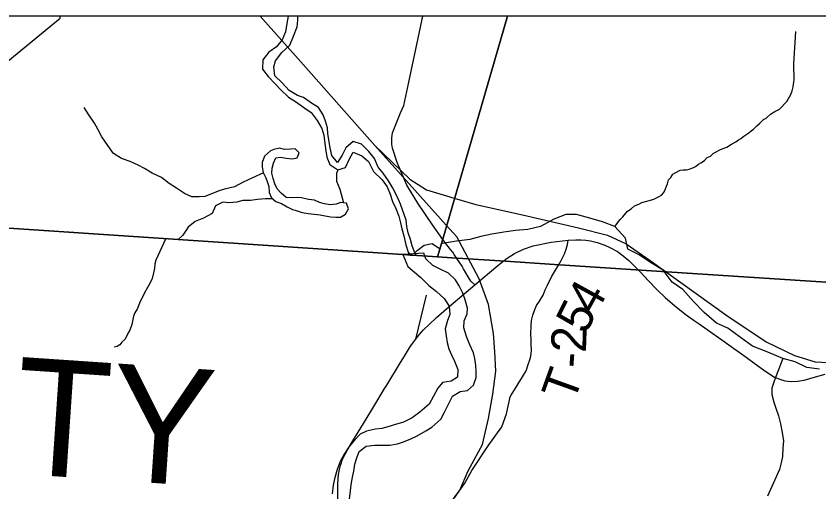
# Model space of a CAD drawing. Extents: x 0 to 44, y -23.8 to 22.
# Drawn here: x 6.018 to 7.321, y 20.128 to 20.9 of the extents above; entities that cross this region are included whole.
import ezdxf

# ---------------------------------------------------------------- set-up
doc = ezdxf.new("R2010")
doc.units = 0
for name, color, linetype in [('Default', 7, 'Continuous'), ('GM_X_County_Road', 7, 'Continuous'), ('GM_X_County_Text', 7, 'Continuous'), ('GM_X_Minor_Lake', 7, 'Continuous'), ('GM_X_Minor_River', 7, 'Continuous'), ('GM_X_Rail_Line', 7, 'Continuous'), ('GM_X_State_Route', 7, 'Continuous'), ('GM_X_Township_Road', 7, 'Continuous'), ('GM_X_Township_Road_Text', 7, 'Continuous'), ('SH_Cut_Line', 7, 'Continuous')]:
    doc.layers.add(name, color=color, linetype=linetype)

msp = doc.modelspace()

# ---------------------------------------------------------------- linework, layer by layer
at = {"layer": 'Default'}
for points in [[(6.8158, 20.9), (2.3497, 20.9), (2.472, 20.6113), (2.8013, 19.8369), (3.0092, 19.3427), (3.0496, 19.2474), (3.1321, 19.0527), (3.1789, 18.9421), (3.455, 18.29), (3.5135, 19.1552), (3.5139, 19.1608), (3.5639, 19.9016), (3.5995, 20.4294), (3.5996, 20.4304), (3.6002, 20.4391), (3.6191, 20.7184), (3.9141, 20.6975), (4.3639, 20.6657), (6.7023, 20.5094), (6.7107, 20.5383)], [(6.0898, 20.9), (5.0097, 20.9), (4.9745, 20.6293), (5.6255, 20.5903), (5.7098, 20.5851), (6.0899, 20.8964)], [(8.9, 20.3521), (8.9, 20.9), (6.8158, 20.9), (6.7107, 20.5383), (6.7023, 20.5094), (6.7257, 20.5079), (6.8124, 20.5023), (6.892, 20.4972), (7.016, 20.4891), (7.4495, 20.4611), (7.6577, 20.4476), (8.6785, 20.3684)]]:
    msp.add_lwpolyline(points, close=True, dxfattribs=at)
msp.add_lwpolyline([(7.4495, 20.4611), (7.016, 20.4891), (6.892, 20.4972), (6.8124, 20.5023), (6.7257, 20.5079), (6.7023, 20.5094), (4.3639, 20.6657), (3.9141, 20.6975), (3.6191, 20.7184), (3.6002, 20.4391), (3.5996, 20.4304), (3.5995, 20.4294), (3.5639, 19.9016), (3.5139, 19.1608), (3.5135, 19.1552), (3.455, 18.29), (3.763, 17.5087), (3.7907, 17.4383), (4.026, 16.9163), (4.1422, 16.6361), (4.3476, 16.1408)], dxfattribs=at)
at = {"layer": 'GM_X_County_Road'}
msp.add_line((6.667, 20.376), (6.6844, 20.4475), dxfattribs=at)
for points in [[(6.7109, 20.5378), (6.694, 20.5615), (6.6703, 20.5965), (6.6525, 20.6256), (6.6474, 20.6369), (6.6366, 20.6627), (6.6294, 20.6856), (6.628, 20.6924), (6.6283, 20.7026), (6.6294, 20.7104), (6.642, 20.7432), (6.6477, 20.7548), (6.6555, 20.7928), (6.6708, 20.8641), (6.6787, 20.9)], [(6.5403, 20.116), (6.5403, 20.1283), (6.5405, 20.141), (6.5411, 20.1499), (6.5417, 20.1559), (6.543, 20.1643), (6.5449, 20.1717), (6.5462, 20.1756), (6.5478, 20.1799), (6.5496, 20.1843), (6.5522, 20.1893), (6.5555, 20.1952), (6.5649, 20.2113), (6.5824, 20.2394), (6.5975, 20.2643), (6.5989, 20.2666), (6.6159, 20.2946), (6.6199, 20.3013), (6.6406, 20.3356), (6.6502, 20.3512), (6.6586, 20.3644), (6.667, 20.376)]]:
    msp.add_lwpolyline(points, dxfattribs=at)
at = {"layer": 'GM_X_Minor_Lake'}
for points in [[(6.4813, 20.605), (6.4756, 20.6056), (6.4665, 20.6052), (6.4566, 20.606), (6.4483, 20.6129), (6.4419, 20.6197), (6.4381, 20.6281), (6.4355, 20.6364), (6.4333, 20.6452), (6.4337, 20.6531), (6.436, 20.6615), (6.4398, 20.6698), (6.4481, 20.6709), (6.4568, 20.6697), (6.4663, 20.6682), (6.4743, 20.6701), (6.4777, 20.6784), (6.4713, 20.6845), (6.4637, 20.6841), (6.4539, 20.6834), (6.4459, 20.6857), (6.4368, 20.6838), (6.4311, 20.6812), (6.4216, 20.6729), (6.4178, 20.6623), (6.4178, 20.6547), (6.4193, 20.6464), (6.4234, 20.6376), (6.4256, 20.6315), (6.4283, 20.6236), (6.429, 20.6141), (6.4331, 20.6053), (6.4399, 20.5993), (6.449, 20.5958), (6.4585, 20.5905), (6.4668, 20.5863), (6.4711, 20.585)], [(6.4711, 20.585), (6.4743, 20.584), (6.4827, 20.5813), (6.4925, 20.5797), (6.502, 20.5785), (6.5118, 20.5774), (6.5198, 20.5758), (6.5289, 20.5743), (6.5372, 20.5739), (6.5451, 20.5738), (6.5531, 20.5787), (6.5577, 20.5874), (6.5547, 20.5965), (6.5456, 20.5977), (6.538, 20.5947), (6.5282, 20.5936), (6.5191, 20.5952), (6.5108, 20.5978), (6.5024, 20.6013), (6.493, 20.6025), (6.4813, 20.605)]]:
    msp.add_lwpolyline(points, dxfattribs=at)
at = {"layer": 'GM_X_Minor_River'}
for p, q in [((6.6799, 20.5152), (6.646, 20.5131)), ((6.6578, 20.512), (6.6677, 20.5114))]:
    msp.add_line(p, q, dxfattribs=at)
for points in [[(6.4601, 20.9), (6.458, 20.8878), (6.4556, 20.8742), (6.4499, 20.8613), (6.4412, 20.85), (6.4283, 20.8413), (6.4187, 20.8288), (6.4183, 20.814), (6.4274, 20.8022)], [(6.4601, 20.9), (6.458, 20.8878), (6.4556, 20.8742), (6.4499, 20.8613), (6.4412, 20.85), (6.4283, 20.8413), (6.4187, 20.8288), (6.4183, 20.814), (6.4274, 20.8022)], [(6.4848, 20.7679), (6.475, 20.7713), (6.4614, 20.7793), (6.4504, 20.7915), (6.438, 20.8033), (6.4365, 20.8174), (6.4396, 20.8276), (6.4498, 20.8408), (6.4624, 20.8529), (6.4685, 20.8673), (6.4746, 20.8828), (6.4758, 20.8935), (6.4758, 20.9)], [(6.9902, 20.5586), (6.9986, 20.57), (7.0032, 20.5745), (7.0109, 20.5835), (7.0167, 20.5876), (7.022, 20.5921), (7.0293, 20.595), (7.0339, 20.5976), (7.0399, 20.5995), (7.0479, 20.6016), (7.0536, 20.6031), (7.062, 20.6072), (7.0659, 20.6094), (7.0697, 20.6139), (7.0721, 20.6196), (7.074, 20.6241), (7.0756, 20.6279), (7.0772, 20.6343), (7.081, 20.6381), (7.0841, 20.6438), (7.0891, 20.6464), (7.0959, 20.6501), (7.1009, 20.6504), (7.1062, 20.6507), (7.1107, 20.6518), (7.1165, 20.654), (7.121, 20.6558), (7.126, 20.6596), (7.1298, 20.6618), (7.1356, 20.6655), (7.1398, 20.6704), (7.1451, 20.673), (7.1497, 20.6771), (7.1535, 20.6794), (7.1616, 20.6838), (7.1658, 20.6853), (7.1719, 20.6875), (7.1795, 20.692), (7.1864, 20.696), (7.1906, 20.699), (7.1944, 20.7013), (7.1994, 20.7054), (7.2074, 20.7106), (7.2116, 20.7136), (7.2154, 20.7166), (7.2208, 20.7218), (7.225, 20.7256), (7.2312, 20.732), (7.2358, 20.7346), (7.2427, 20.7409), (7.2495, 20.745), (7.2575, 20.7491), (7.2691, 20.7615), (7.276, 20.7728), (7.278, 20.7789), (7.2796, 20.7853), (7.2808, 20.7929), (7.2812, 20.7971), (7.2809, 20.8017), (7.281, 20.807), (7.2806, 20.8108), (7.2804, 20.8226), (7.284, 20.875)], [(6.4274, 20.8022), (6.4387, 20.7901), (6.4481, 20.7802), (6.4602, 20.7687), (6.4719, 20.7615), (6.487, 20.7504), (6.4972, 20.7436), (6.507, 20.7306), (6.5146, 20.7177), (6.5179, 20.7067), (6.5194, 20.6934), (6.5209, 20.6816), (6.5224, 20.6714), (6.5276, 20.6592), (6.5405, 20.6508), (6.553, 20.6542), (6.5587, 20.6671), (6.5656, 20.6792), (6.5792, 20.6734), (6.5905, 20.6639), (6.5984, 20.648), (6.6124, 20.6343), (6.6207, 20.6232), (6.6256, 20.6114), (6.6293, 20.5993), (6.6346, 20.5879), (6.6395, 20.5754), (6.6421, 20.5647), (6.6443, 20.5549), (6.6477, 20.5435), (6.6511, 20.5287), (6.6548, 20.5169), (6.6578, 20.512)], [(6.6677, 20.5114), (6.6662, 20.5142), (6.6609, 20.5271), (6.6583, 20.5377), (6.6549, 20.5484), (6.6527, 20.5586), (6.6512, 20.5692), (6.6422, 20.5951), (6.6369, 20.6072), (6.6294, 20.6217), (6.6226, 20.6327), (6.6143, 20.6452), (6.606, 20.6551), (6.6, 20.6688), (6.5906, 20.6802), (6.5789, 20.6924), (6.5653, 20.6966), (6.5535, 20.6864), (6.5478, 20.6743), (6.5398, 20.6626), (6.5307, 20.674), (6.5281, 20.6865), (6.5259, 20.6994), (6.5244, 20.7093), (6.5237, 20.7188), (6.5203, 20.7294), (6.5169, 20.7397), (6.509, 20.7519), (6.4977, 20.7587), (6.4848, 20.7679)], [(6.4196, 20.6457), (6.4007, 20.6373), (6.387, 20.6306), (6.373, 20.623), (6.3589, 20.6197), (6.3491, 20.617), (6.3373, 20.6122), (6.3248, 20.6073), (6.3153, 20.6066), (6.3036, 20.6066), (6.2915, 20.612), (6.2786, 20.6207), (6.2669, 20.6287), (6.2544, 20.6383), (6.2389, 20.6452), (6.2268, 20.6528), (6.2163, 20.6581), (6.2034, 20.6643), (6.1894, 20.6692), (6.1765, 20.6772), (6.1671, 20.6902), (6.1573, 20.7039), (6.1509, 20.7164), (6.1457, 20.7263), (6.1366, 20.74), (6.1287, 20.7518)], [(6.5405, 20.6508), (6.5382, 20.6448), (6.5385, 20.6323), (6.5438, 20.619), (6.5498, 20.5972)], [(6.4352, 20.6035), (6.4229, 20.6035), (6.41, 20.6024), (6.3986, 20.6009), (6.3865, 20.6006), (6.3767, 20.5984), (6.3638, 20.5969), (6.3536, 20.5981), (6.3422, 20.5924), (6.3364, 20.5799), (6.3224, 20.572), (6.3091, 20.5667), (6.2977, 20.5577), (6.289, 20.5444), (6.2808, 20.5372)], [(7.322, 20.3275), (7.3019, 20.3299), (7.283, 20.3391), (7.263, 20.3445), (7.2384, 20.3549), (7.2134, 20.3645), (7.1938, 20.3787), (7.1734, 20.394), (7.1549, 20.4021), (7.1353, 20.4193), (7.118, 20.4368), (7.1007, 20.4563), (7.0829, 20.4685), (7.0686, 20.4876), (7.0479, 20.5002), (7.0294, 20.5129), (7.0112, 20.5217), (7.0076, 20.5399), (6.9902, 20.5586), (6.9702, 20.566), (6.9497, 20.5721), (6.9278, 20.5783), (6.9107, 20.578), (6.8913, 20.5705), (6.8693, 20.5585), (6.8491, 20.5537), (6.829, 20.5523), (6.8097, 20.5493), (6.7903, 20.546), (6.7728, 20.5427), (6.755, 20.5378), (6.733, 20.5349), (6.7105, 20.5309)], [(6.2609, 20.5383), (6.2452, 20.5039), (6.2436, 20.4982), (6.2427, 20.4906), (6.2411, 20.4834), (6.2391, 20.4743), (6.236, 20.4671), (6.2314, 20.4599), (6.2267, 20.4513), (6.2213, 20.4399), (6.219, 20.4358), (6.2151, 20.4256), (6.2108, 20.4184), (6.2088, 20.4135), (6.2064, 20.3995), (6.2029, 20.3904), (6.2002, 20.3862), (6.1971, 20.3794), (6.1948, 20.3753), (6.1898, 20.3712), (6.1867, 20.367), (6.1821, 20.364), (6.1775, 20.363)], [(6.6654, 20.516), (6.6692, 20.5195), (6.6806, 20.5286), (6.6935, 20.5312), (6.7056, 20.5231), (6.7073, 20.5228)], [(6.646, 20.5131), (6.6542, 20.494), (6.6648, 20.4845), (6.6751, 20.4758), (6.6884, 20.4632), (6.7005, 20.4533), (6.7131, 20.4419), (6.7214, 20.4297), (6.7222, 20.416), (6.7187, 20.4065), (6.7149, 20.3928), (6.7161, 20.3814), (6.718, 20.3704), (6.7206, 20.3605), (6.7248, 20.3503), (6.7301, 20.3404), (6.7354, 20.3267), (6.735, 20.3145), (6.7244, 20.3081), (6.7103, 20.3058), (6.7027, 20.2963), (6.6958, 20.2837), (6.689, 20.2704), (6.6738, 20.2575), (6.6609, 20.2484), (6.6472, 20.2416), (6.6342, 20.2374), (6.6217, 20.234), (6.6118, 20.2313), (6.6019, 20.2298), (6.5871, 20.2268), (6.5768, 20.2219), (6.5673, 20.2124), (6.559, 20.2021), (6.551, 20.1892), (6.5441, 20.1774), (6.5392, 20.1645), (6.535, 20.1493), (6.5331, 20.139), (6.5312, 20.1253)], [(6.5592, 20.1164), (6.5608, 20.1301), (6.5619, 20.1396), (6.5642, 20.1522), (6.5665, 20.1617), (6.568, 20.1731), (6.5711, 20.1833), (6.5749, 20.1936), (6.5867, 20.2023), (6.6003, 20.2042), (6.6125, 20.2038), (6.6247, 20.2038), (6.6372, 20.2061), (6.6471, 20.2095), (6.6589, 20.2141), (6.6691, 20.219), (6.6836, 20.2274), (6.6931, 20.2331), (6.7076, 20.246), (6.7136, 20.2578), (6.7201, 20.2703), (6.7266, 20.2836), (6.7388, 20.2912), (6.7509, 20.2927), (6.7608, 20.3014), (6.765, 20.314), (6.765, 20.3235), (6.7646, 20.3334), (6.7631, 20.3444), (6.7605, 20.3539), (6.7548, 20.3665), (6.7491, 20.3802), (6.7449, 20.3946), (6.7453, 20.4056), (6.7502, 20.417), (6.751, 20.4265), (6.7472, 20.4399), (6.7434, 20.4505), (6.7374, 20.4627), (6.7313, 20.4722), (6.7203, 20.4828), (6.7066, 20.4893), (6.6948, 20.4954), (6.6834, 20.5061), (6.6799, 20.5152)], [(7.263, 20.3445), (7.2493, 20.3092), (7.2447, 20.2966), (7.2451, 20.2864), (7.2481, 20.2738), (7.2515, 20.2643), (7.2557, 20.2514), (7.2587, 20.2388), (7.2614, 20.2244), (7.2636, 20.2111), (7.2629, 20.1989), (7.2621, 20.1856), (7.2602, 20.1753), (7.2571, 20.1643), (7.2499, 20.1476), (7.2381, 20.1214)]]:
    msp.add_lwpolyline(points, dxfattribs=at)
at = {"layer": 'GM_X_Rail_Line'}
msp.add_line((6.7166, 20.5611), (6.6008, 20.69), dxfattribs=at)
for points in [[(6.6008, 20.69), (6.485, 20.8208), (6.4143, 20.9)], [(6.6008, 20.69), (6.6573, 20.6353), (6.6842, 20.6179), (6.7168, 20.6086), (6.7295, 20.6047)], [(6.7295, 20.6047), (6.7644, 20.5946), (6.84, 20.5777), (6.9312, 20.5568), (6.9782, 20.5449), (7.0086, 20.5308), (7.0474, 20.5035), (7.1721, 20.4142), (7.2358, 20.3715), (7.2818, 20.3494), (7.315, 20.3394), (7.3263, 20.3384), (7.3507, 20.3379), (7.3763, 20.3478), (7.4044, 20.3703), (7.4197, 20.4001), (7.4343, 20.437), (7.4504, 20.4841)], [(6.0065, 19.4423), (6.0411, 19.4544), (6.0732, 19.4729), (6.1062, 19.4986), (6.1416, 19.5292), (6.395, 19.7779), (6.6878, 20.0692), (6.7143, 20.0982), (6.7384, 20.1312), (6.7521, 20.1626), (6.7752, 20.2051), (6.7849, 20.2473), (6.7922, 20.2869), (6.7971, 20.3238), (6.7954, 20.3554), (6.7929, 20.385), (6.7849, 20.432), (6.7699, 20.4736), (6.7338, 20.5421), (6.7166, 20.5611)]]:
    msp.add_lwpolyline(points, dxfattribs=at)
at = {"layer": 'GM_X_State_Route'}
for points in [[(6.9141, 20.5367), (6.9267, 20.537), (6.9347, 20.5369), (6.9431, 20.5364), (6.9508, 20.5354), (6.9616, 20.5328), (6.9738, 20.5284), (6.9819, 20.5248), (6.9943, 20.518), (7.0037, 20.5113), (7.013, 20.5034), (7.0287, 20.4878), (7.0328, 20.4833), (7.0442, 20.471), (7.0581, 20.4565), (7.0716, 20.4434), (7.0875, 20.4298), (7.1057, 20.4156), (7.1186, 20.4064), (7.127, 20.4006), (7.1675, 20.372), (7.2032, 20.3467), (7.2177, 20.3361), (7.2352, 20.3235), (7.2492, 20.3142), (7.2579, 20.3109), (7.2658, 20.3084), (7.277, 20.3072), (7.2868, 20.3078), (7.2974, 20.3095), (7.3158, 20.3148), (7.3317, 20.3193)], [(6.7629, 20.4639), (6.8004, 20.4956), (6.8085, 20.502), (6.8155, 20.5073), (6.8273, 20.5148), (6.842, 20.522), (6.8574, 20.5274), (6.8866, 20.5335), (6.9141, 20.5367)], [(6.667, 20.376), (6.6719, 20.3824), (6.6794, 20.3909), (6.6887, 20.4), (6.7009, 20.4111), (6.7208, 20.4282), (6.7629, 20.4639)], [(6.5403, 20.116), (6.5403, 20.1283), (6.5405, 20.141), (6.5411, 20.1499), (6.5417, 20.1559), (6.543, 20.1643), (6.5449, 20.1717), (6.5462, 20.1756), (6.5478, 20.1799), (6.5496, 20.1843), (6.5522, 20.1893), (6.5555, 20.1952), (6.5649, 20.2113), (6.5824, 20.2394), (6.5975, 20.2643), (6.5989, 20.2666), (6.6159, 20.2946), (6.6199, 20.3013), (6.6406, 20.3356), (6.6502, 20.3512), (6.6586, 20.3644), (6.667, 20.376)]]:
    msp.add_lwpolyline(points, dxfattribs=at)
at = {"layer": 'GM_X_Township_Road'}
for points in [[(6.7447, 20.4901), (6.7423, 20.4943), (6.7339, 20.5069), (6.7295, 20.5133), (6.7269, 20.5173), (6.7236, 20.5215), (6.7174, 20.5291), (6.7109, 20.5378)], [(6.8402, 20.3149), (6.8464, 20.3247), (6.8492, 20.335), (6.8519, 20.3425), (6.8535, 20.3483), (6.8549, 20.3577), (6.8543, 20.3677), (6.8542, 20.3747), (6.8536, 20.385), (6.8543, 20.3971), (6.8549, 20.4062), (6.8569, 20.4148), (6.86, 20.4239), (6.8631, 20.4307), (6.8676, 20.4376), (6.8736, 20.4474), (6.8772, 20.4562), (6.8806, 20.4636), (6.8874, 20.477), (6.8984, 20.4962), (6.9031, 20.5035), (6.9084, 20.5142), (6.911, 20.5217), (6.9131, 20.5295), (6.9141, 20.5367)], [(6.7629, 20.4639), (6.7566, 20.4698), (6.7523, 20.477), (6.7447, 20.4901)], [(6.73, 20.1188), (6.7468, 20.1426), (6.758, 20.1631), (6.7847, 20.2028), (6.8068, 20.2337), (6.8144, 20.255), (6.8194, 20.2799), (6.8199, 20.2814), (6.8216, 20.2853), (6.8402, 20.3149)]]:
    msp.add_lwpolyline(points, dxfattribs=at)
at = {"layer": 'SH_Cut_Line'}
for points in [[(4.3476, 16.1408), (4.1422, 16.6361), (4.026, 16.9163), (3.7907, 17.4383), (3.763, 17.5087), (3.455, 18.29), (3.5135, 19.1552), (3.5139, 19.1608), (3.5639, 19.9016), (3.5995, 20.4294), (3.5996, 20.4304), (3.6002, 20.4391), (3.6191, 20.7184), (3.9141, 20.6975), (4.3639, 20.6657), (6.7023, 20.5094), (6.7107, 20.5383), (6.8158, 20.9), (2.1, 20.9), (2.1, 14.1)], [(8.9, 20.9), (6.8158, 20.9), (6.7107, 20.5383), (6.7023, 20.5094), (4.3639, 20.6657), (3.9141, 20.6975), (3.6191, 20.7184), (3.6002, 20.4391), (3.5996, 20.4304), (3.5995, 20.4294), (3.5639, 19.9016), (3.5139, 19.1608), (3.5135, 19.1552), (3.455, 18.29), (3.763, 17.5087), (3.7907, 17.4383), (4.026, 16.9163), (4.1422, 16.6361), (4.3476, 16.1408)]]:
    msp.add_lwpolyline(points, dxfattribs=at)

# ---------------------------------------------------------------- texts
at = {"layer": 'GM_X_County_Text'}
msp.add_text('LAWRENCE COUNTY', height=0.189394, rotation=356.1322, dxfattribs=at).set_placement((3.7646, 20.3102))
at = {"layer": 'GM_X_Township_Road_Text'}
for s, rotation, p in [('4', 61.0523, (6.9582, 20.413)), ('5', 63.4396, (6.9428, 20.3822)), ('2', 87.977, (6.9431, 20.3534)), ('-', 85.7957, (6.9413, 20.3278)), ('T', 70.1805, (6.9234, 20.2714))]:
    msp.add_text(s, height=0.0568, rotation=rotation, dxfattribs=at).set_placement(p)

doc.saveas('drawing.dxf')
